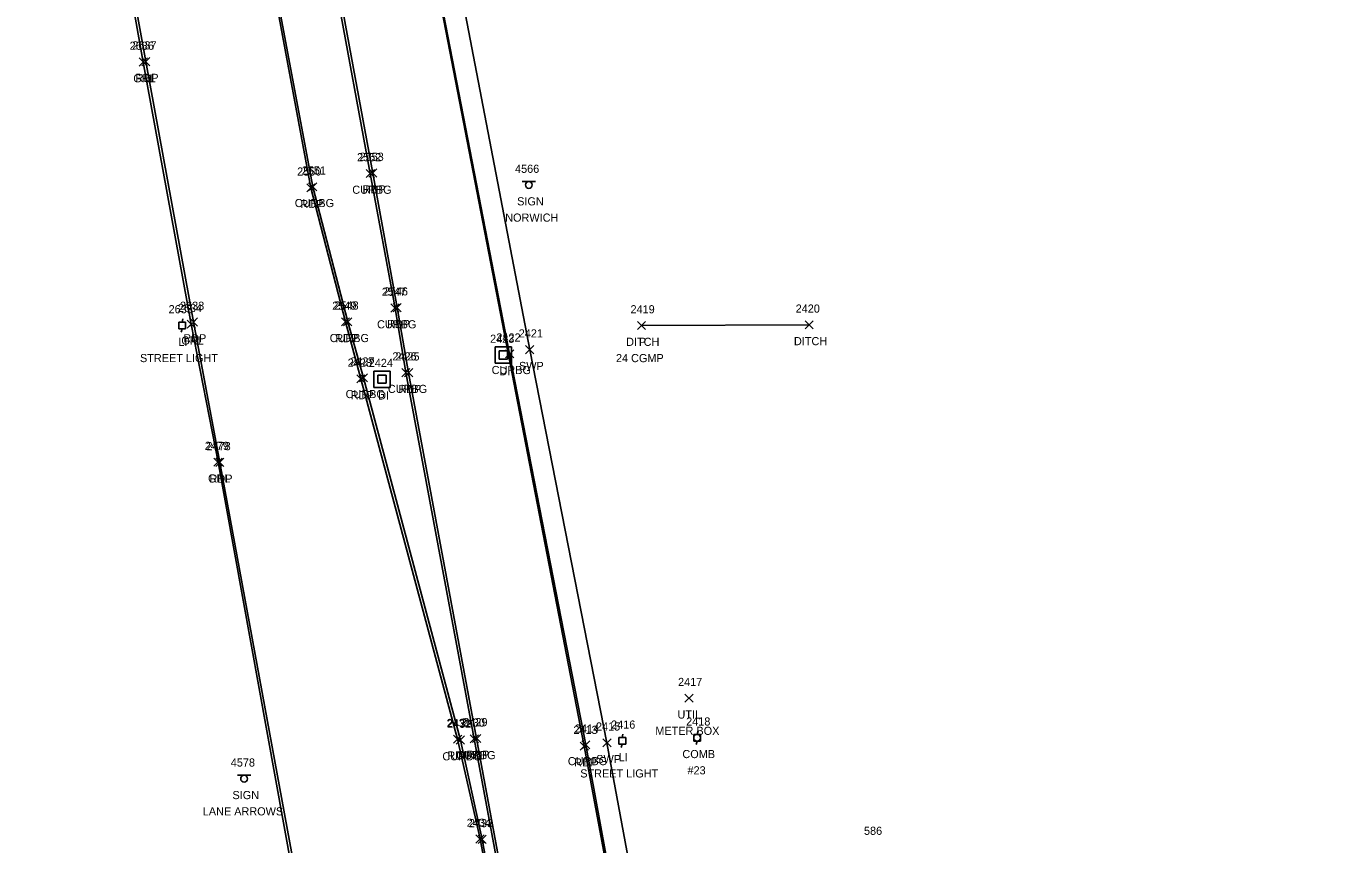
# Model space of a CAD drawing. Extents: x 1690689 to 1696275, y 438760 to 444007.
# Drawn here: x 1691233 to 1691552.4, y 440726.5 to 440927.5 of the extents above; entities that cross this region are included whole.
import ezdxf

# ---------------------------------------------------------------- set-up
doc = ezdxf.new("R2010")
doc.units = 0
for name, color, linetype in [('D_A', 7, 'Continuous'), ('D_C', 7, 'Continuous'), ('D_I', 7, 'Continuous'), ('D_TIC', 7, 'Continuous'), ('DD', 7, 'Continuous'), ('DS', 7, 'Continuous'), ('M_I', 7, 'Continuous'), ('P_A', 7, 'Continuous'), ('P_I', 7, 'Continuous'), ('P_TIC', 7, 'Continuous'), ('PET', 7, 'Continuous'), ('R_A', 7, 'Continuous'), ('R_I', 7, 'Continuous'), ('R_TIC', 7, 'Continuous'), ('RC', 7, 'Continuous'), ('RGR', 7, 'Continuous'), ('RSW', 7, 'Continuous'), ('S_A', 7, 'Continuous'), ('S_C', 7, 'Continuous'), ('S_I', 7, 'Continuous'), ('SSGN', 7, 'Continuous'), ('U_A', 7, 'Continuous'), ('U_C', 7, 'Continuous'), ('U_I', 7, 'Continuous'), ('UDEFAULT', 7, 'Continuous'), ('ULP', 7, 'Continuous'), ('UP', 7, 'Continuous')]:
    doc.layers.add(name, color=color, linetype=linetype)

msp = doc.modelspace()

# ---------------------------------------------------------------- linework, layer by layer
at = {"layer": 'D_TIC'}
for points in [[(1691383.37, 440852.89), (1691385.37, 440854.89)], [(1691385.37, 440852.89), (1691383.37, 440854.89)], [(1691383.37, 440852.89), (1691385.37, 440854.89)], [(1691385.37, 440852.89), (1691383.37, 440854.89)], [(1691424.61, 440853.06), (1691426.61, 440855.06)], [(1691426.61, 440853.06), (1691424.61, 440855.06)]]:
    msp.add_lwpolyline(points, dxfattribs=at)
at = {"layer": 'DD'}
msp.add_lwpolyline([(1691384.37, 440853.89), (1691425.61, 440854.06)], dxfattribs=at)
at = {"layer": 'DS'}
for p, q in [((1691348.4, 440848.65), (1691352.4, 440848.65)), ((1691348.4, 440844.65), (1691348.4, 440848.65)), ((1691349.4, 440845.65), (1691349.4, 440847.65)), ((1691349.4, 440847.65), (1691351.4, 440847.65)), ((1691350.41, 440846.65), (1691350.41, 440846.65)), ((1691350.41, 440846.65), (1691350.41, 440846.65)), ((1691351.4, 440847.65), (1691351.4, 440845.65)), ((1691352.4, 440848.65), (1691352.4, 440844.65)), ((1691352.4, 440844.65), (1691348.4, 440844.65)), ((1691351.4, 440845.65), (1691349.4, 440845.65)), ((1691318.57, 440842.7), (1691322.57, 440842.7)), ((1691318.57, 440838.7), (1691318.57, 440842.7)), ((1691319.57, 440839.7), (1691319.57, 440841.7)), ((1691319.57, 440841.7), (1691321.57, 440841.7)), ((1691320.57, 440840.71), (1691320.57, 440840.71)), ((1691320.57, 440840.71), (1691320.57, 440840.71)), ((1691321.57, 440841.7), (1691321.57, 440839.7)), ((1691322.57, 440842.7), (1691322.57, 440838.7)), ((1691322.57, 440838.7), (1691318.57, 440838.7)), ((1691321.57, 440839.7), (1691319.57, 440839.7))]:
    msp.add_line(p, q, dxfattribs=at)
at = {"layer": 'P_TIC'}
for points in [[(1691261.49, 440917.74), (1691263.49, 440919.74)], [(1691263.49, 440917.74), (1691261.49, 440919.74)], [(1691317.31, 440890.37), (1691319.31, 440892.37)], [(1691319.31, 440890.37), (1691317.31, 440892.37)], [(1691302.05, 440886.74), (1691304.05, 440888.74)], [(1691304.05, 440886.74), (1691302.05, 440888.74)], [(1691323.31, 440857.29), (1691325.31, 440859.29)], [(1691325.31, 440857.29), (1691323.31, 440859.29)], [(1691273.23, 440853.76), (1691275.23, 440855.76)], [(1691275.23, 440853.76), (1691273.23, 440855.76)], [(1691273.23, 440853.76), (1691275.23, 440855.76)], [(1691275.23, 440853.76), (1691273.23, 440855.76)], [(1691310.61, 440853.78), (1691312.61, 440855.78)], [(1691312.61, 440853.78), (1691310.61, 440855.78)], [(1691326.11, 440841.3), (1691328.11, 440843.3)], [(1691328.11, 440841.3), (1691326.11, 440843.3)], [(1691326.11, 440841.3), (1691328.11, 440843.3)], [(1691328.11, 440841.3), (1691326.11, 440843.3)], [(1691314.38, 440839.77), (1691316.38, 440841.77)], [(1691316.38, 440839.77), (1691314.38, 440841.77)], [(1691314.38, 440839.77), (1691316.38, 440841.77)], [(1691316.38, 440839.77), (1691314.38, 440841.77)], [(1691279.68, 440819.26), (1691281.68, 440821.26)], [(1691281.68, 440819.26), (1691279.68, 440821.26)], [(1691338.16, 440751.24), (1691340.16, 440753.24)], [(1691340.16, 440751.24), (1691338.16, 440753.24)], [(1691342.83, 440751.44), (1691344.83, 440753.44)], [(1691344.83, 440751.44), (1691342.83, 440753.44)], [(1691369.31, 440749.54), (1691371.31, 440751.54)], [(1691371.31, 440749.54), (1691369.31, 440751.54)], [(1691343.67, 440726.73), (1691345.67, 440728.73)], [(1691345.67, 440726.73), (1691343.67, 440728.73)]]:
    msp.add_lwpolyline(points, dxfattribs=at)
at = {"layer": 'PET'}
for points in [[(1691274.23, 440854.76), (1691262.49, 440918.74), (1691249.64, 440989.69), (1691246.21, 441008.07), (1691242.26, 441033.57), (1691238.51, 441080.26), (1691233.04, 441128.02)], [(1691552.42, 440436.47), (1691508.96, 440428.4), (1691494.48, 440424.84), (1691487.53, 440422.16), (1691479.98, 440421.74), (1691470.17, 440422.5), (1691465.43, 440423.73), (1691457.75, 440426.39), (1691450.59, 440430.36), (1691444.98, 440434.77), (1691439.4, 440439.84), (1691432.83, 440448.46), (1691425.81, 440467.29), (1691416.92, 440505.6), (1691412.15, 440527.64), (1691404.42, 440565.6), (1691397.74, 440602.52), (1691382.41, 440685.3), (1691370.31, 440750.54), (1691330.06, 440958.54), (1691316.82, 441030.69), (1691309.01, 441068.57), (1691294.14, 441127.58)], [(1691315.38, 440840.77), (1691311.61, 440854.78), (1691303.05, 440887.74), (1691293.73, 440938.05), (1691282.96, 440996.72), (1691276.31, 441056.08), (1691276.5, 441078.72), (1691277.07, 441079.98)], [(1691327.11, 440842.3), (1691324.31, 440858.29), (1691318.31, 440891.37), (1691310.01, 440936.22), (1691297.98, 441000.51), (1691285.01, 441057.44), (1691279.75, 441079.06), (1691279.06, 441080.28), (1691277.81, 441080.8), (1691277.07, 441079.98)], [(1691350.23, 440434.31), (1691349.02, 440445.67), (1691341.53, 440488.54), (1691328.03, 440562.61), (1691315.34, 440632.97), (1691299.08, 440720.53), (1691280.68, 440820.26), (1691274.23, 440854.76)], [(1691315.38, 440840.77), (1691339.16, 440752.24), (1691344.67, 440727.73), (1691359.12, 440649.27), (1691368.01, 440600.75), (1691385.38, 440506.23), (1691396.38, 440445.66), (1691403.64, 440405.97), (1691404.52, 440404.92)], [(1691327.11, 440842.3), (1691343.83, 440752.44), (1691362.78, 440649.9), (1691372.44, 440596.72), (1691388.92, 440507.28), (1691399.19, 440450.17), (1691407.2, 440406.4), (1691406.31, 440404.65), (1691404.52, 440404.92)]]:
    msp.add_lwpolyline(points, dxfattribs=at)
at = {"layer": 'R_TIC'}
for points in [[(1691260.88, 440917.64), (1691262.88, 440919.64)], [(1691262.88, 440917.64), (1691260.88, 440919.64)], [(1691316.69, 440890.26), (1691318.69, 440892.26)], [(1691318.69, 440890.26), (1691316.69, 440892.26)], [(1691302.54, 440886.99), (1691304.54, 440888.99)], [(1691304.54, 440886.99), (1691302.54, 440888.99)], [(1691322.78, 440857.19), (1691324.78, 440859.19)], [(1691324.78, 440857.19), (1691322.78, 440859.19)], [(1691272.69, 440853.21), (1691274.69, 440855.21)], [(1691274.69, 440853.21), (1691272.69, 440855.21)], [(1691272.69, 440853.21), (1691274.69, 440855.21)], [(1691274.69, 440853.21), (1691272.69, 440855.21)], [(1691311.13, 440853.82), (1691313.13, 440855.82)], [(1691313.13, 440853.82), (1691311.13, 440855.82)], [(1691350.95, 440845.96), (1691352.95, 440847.96)], [(1691352.95, 440845.96), (1691350.95, 440847.96)], [(1691355.89, 440846.96), (1691357.89, 440848.96)], [(1691357.89, 440846.96), (1691355.89, 440848.96)], [(1691325.44, 440841.32), (1691327.44, 440843.32)], [(1691327.44, 440841.32), (1691325.44, 440843.32)], [(1691325.44, 440841.32), (1691327.44, 440843.32)], [(1691327.44, 440841.32), (1691325.44, 440843.32)], [(1691315.03, 440840.06), (1691317.03, 440842.06)], [(1691317.03, 440840.06), (1691315.03, 440842.06)], [(1691315.03, 440840.06), (1691317.03, 440842.06)], [(1691317.03, 440840.06), (1691315.03, 440842.06)], [(1691279.26, 440819.33), (1691281.26, 440821.33)], [(1691281.26, 440819.33), (1691279.26, 440821.33)], [(1691338.83, 440751.04), (1691340.83, 440753.04)], [(1691340.83, 440751.04), (1691338.83, 440753.04)], [(1691342.27, 440751.33), (1691344.27, 440753.33)], [(1691344.27, 440751.33), (1691342.27, 440753.33)], [(1691369.67, 440749.86), (1691371.67, 440751.86)], [(1691371.67, 440749.86), (1691369.67, 440751.86)], [(1691374.88, 440750.37), (1691376.88, 440752.37)], [(1691376.88, 440750.37), (1691374.88, 440752.37)], [(1691344.19, 440726.63), (1691346.19, 440728.63)], [(1691346.19, 440726.63), (1691344.19, 440728.63)]]:
    msp.add_lwpolyline(points, dxfattribs=at)
at = {"layer": 'RC'}
for points in [[(1691450.76, 440430.58), (1691444.92, 440435.07), (1691439.78, 440439.75), (1691432.93, 440448.9), (1691426.12, 440467.24), (1691417.19, 440505.54), (1691412.4, 440527.61), (1691405.01, 440565.67), (1691398.01, 440602.6), (1691382.66, 440685.49), (1691370.67, 440750.86), (1691351.95, 440846.96), (1691330.25, 440958.42), (1691317.04, 441030.78), (1691309.36, 441068.61), (1691294.46, 441127.62), (1691280.16, 441186.14), (1691271.8, 441225.57)], [(1691316.03, 440841.06), (1691312.13, 440854.82), (1691303.54, 440887.99), (1691294.13, 440938.24), (1691283.53, 440996.84), (1691276.71, 441056.25), (1691277.13, 441078.83), (1691277.37, 441079.82)], [(1691326.44, 440842.32), (1691323.78, 440858.19), (1691317.69, 440891.26), (1691309.38, 440936.25), (1691297.2, 441000.25), (1691284.66, 441057.25), (1691279.32, 441078.94), (1691278.99, 441079.94), (1691278.1, 441080.23), (1691277.37, 441079.82)], [(1691316.03, 440841.06), (1691339.83, 440752.04), (1691345.19, 440727.63), (1691359.75, 440649.46), (1691368.41, 440600.85), (1691369.54, 440598.21)], [(1691326.44, 440842.32), (1691343.27, 440752.33), (1691362.34, 440649.71), (1691372.07, 440596.75), (1691388.57, 440507.07), (1691399.02, 440450.03), (1691406.75, 440406.47), (1691406.03, 440405.14), (1691404.87, 440405.37)]]:
    msp.add_lwpolyline(points, dxfattribs=at)
at = {"layer": 'RGR'}
for points in [[(1691273.69, 440854.21), (1691261.88, 440918.64), (1691249.24, 440989.46), (1691244.95, 441007.8), (1691238.22, 441030.27)], [(1691349.43, 440432.67), (1691348.1, 440445.44), (1691340.7, 440488.56), (1691327.21, 440562.16), (1691314.3, 440632.73), (1691298.42, 440720.43), (1691280.26, 440820.33), (1691273.69, 440854.21)]]:
    msp.add_lwpolyline(points, dxfattribs=at)
at = {"layer": 'RSW'}
msp.add_lwpolyline([(1691443.18, 440443.49), (1691437.15, 440451.8), (1691431.59, 440467.18), (1691422.3, 440506.42), (1691417.59, 440529.04), (1691409.95, 440566.67), (1691402.99, 440604.6), (1691387.94, 440685.95), (1691375.88, 440751.37), (1691356.89, 440847.96), (1691335.56, 440959.35), (1691322.05, 441031.91), (1691314.28, 441069.9), (1691299.65, 441129.23)], dxfattribs=at)
at = {"layer": 'SSGN'}
for p, q in [((1691355.02, 440889.26), (1691358.35, 440889.26)), ((1691356.66, 440888.43), (1691356.66, 440888.43)), ((1691285.02, 440743.37), (1691288.35, 440743.37)), ((1691286.67, 440742.54), (1691286.67, 440742.54))]:
    msp.add_line(p, q, dxfattribs=at)
for centre in [(1691356.66, 440888.43), (1691286.67, 440742.54)]:
    msp.add_circle(centre, 0.833, dxfattribs=at)
at = {"layer": 'UDEFAULT'}
for points in [[(1691395.06, 440761.31), (1691397.06, 440763.31)], [(1691397.06, 440761.31), (1691395.06, 440763.31)]]:
    msp.add_lwpolyline(points, dxfattribs=at)
at = {"layer": 'ULP'}
for p, q in [((1691270.58, 440853.07), (1691270.58, 440854.74)), ((1691270.58, 440854.74), (1691272.25, 440854.74)), ((1691272.25, 440853.07), (1691270.58, 440853.07)), ((1691271.16, 440852.24), (1691271.41, 440853.07)), ((1691271.58, 440855.57), (1691271.41, 440854.74)), ((1691271.41, 440853.9), (1691271.41, 440853.9)), ((1691272.25, 440854.74), (1691272.25, 440853.07)), ((1691378.81, 440751.01), (1691378.81, 440752.67)), ((1691378.81, 440752.67), (1691380.48, 440752.67)), ((1691380.48, 440751.01), (1691378.81, 440751.01)), ((1691379.4, 440750.17), (1691379.65, 440751.01)), ((1691379.81, 440753.51), (1691379.65, 440752.67)), ((1691379.65, 440751.84), (1691379.65, 440751.84)), ((1691380.48, 440752.67), (1691380.48, 440751.01))]:
    msp.add_line(p, q, dxfattribs=at)
at = {"layer": 'UP'}
for p, q in [((1691398.29, 440754.27), (1691398.04, 440753.43)), ((1691397.21, 440751.77), (1691397.21, 440753.43)), ((1691397.21, 440753.43), (1691398.88, 440753.43)), ((1691398.88, 440751.77), (1691397.21, 440751.77)), ((1691397.79, 440750.93), (1691398.04, 440751.77)), ((1691398.04, 440752.6), (1691398.04, 440752.6)), ((1691398.88, 440753.43), (1691398.88, 440751.77))]:
    msp.add_line(p, q, dxfattribs=at)
msp.add_circle((1691398.04, 440752.6), 0.833, dxfattribs=at)

# ---------------------------------------------------------------- texts
at = {"layer": 'D_A'}
for s, p in [('DITCH', (1691380.6, 440848.89)), ('P', (1691383.74, 440848.89)), ('DITCH', (1691421.85, 440849.06)), ('DI', (1691349.46, 440841.65)), ('DI', (1691319.63, 440835.71))]:
    msp.add_text(s, height=2, dxfattribs=at).set_placement(p)
at = {"layer": 'D_C'}
msp.add_text('24 CGMP', height=2, dxfattribs=at).set_placement((1691378.09, 440844.89))
at = {"layer": 'D_I'}
for s, p in [('2420', (1691422.27, 440857.06)), ('2419', (1691381.67, 440856.89)), ('2419', (1691381.67, 440856.89)), ('2423', (1691347.15, 440849.65)), ('2424', (1691317.31, 440843.71))]:
    msp.add_text(s, height=2, dxfattribs=at).set_placement(p)
at = {"layer": 'M_I'}
msp.add_text('586', height=2, dxfattribs=at).set_placement((1691439.07, 440728.74))
at = {"layer": 'P_A'}
for p in [(1691259.98, 440913.74), (1691315.8, 440886.37), (1691300.53, 440882.74), (1691321.8, 440853.29), (1691271.72, 440849.76), (1691271.72, 440849.76), (1691309.1, 440849.78), (1691312.87, 440835.77), (1691312.87, 440835.77), (1691324.6, 440837.3), (1691324.6, 440837.3), (1691278.17, 440815.26), (1691336.65, 440747.24), (1691341.31, 440747.44), (1691367.8, 440745.54)]:
    msp.add_text('RDP', height=2, dxfattribs=at).set_placement(p)
at = {"layer": 'P_I'}
for s, p in [('2637', (1691259.19, 440921.74)), ('2553', (1691315.05, 440894.37)), ('2550', (1691299.7, 440890.74)), ('2546', (1691321, 440861.29)), ('2633', (1691270.92, 440857.76)), ('2633', (1691270.92, 440857.76)), ('2549', (1691308.34, 440857.78)), ('2425', (1691323.85, 440845.3)), ('2425', (1691323.85, 440845.3)), ('2428', (1691312.12, 440843.77)), ('2428', (1691312.12, 440843.77)), ('2478', (1691277.42, 440823.26)), ('2431', (1691336.47, 440755.24)), ('2429', (1691340.56, 440755.44)), ('2413', (1691367.62, 440753.54)), ('2434', (1691341.41, 440730.73))]:
    msp.add_text(s, height=2, dxfattribs=at).set_placement(p)
at = {"layer": 'R_A'}
for s, p in [('GRL', (1691259.42, 440913.64)), ('CURBG', (1691313.27, 440886.26)), ('CURBG', (1691299.12, 440882.99)), ('CURBG', (1691319.36, 440853.19)), ('GRL', (1691271.23, 440849.21)), ('GRL', (1691271.23, 440849.21)), ('CURBG', (1691307.71, 440849.82)), ('CURBG', (1691347.53, 440841.96)), ('SWP', (1691354.25, 440842.96)), ('CURBG', (1691311.62, 440836.06)), ('CURBG', (1691311.62, 440836.06)), ('CURBG', (1691322.02, 440837.32)), ('CURBG', (1691322.02, 440837.32)), ('GRL', (1691277.8, 440815.33)), ('CURBG', (1691335.41, 440747.04)), ('CURBG', (1691338.85, 440747.33)), ('CURBG', (1691366.26, 440745.86)), ('SWP', (1691373.25, 440746.37))]:
    msp.add_text(s, height=2, dxfattribs=at).set_placement(p)
at = {"layer": 'R_I'}
for s, p in [('2636', (1691258.52, 440921.64)), ('2552', (1691314.43, 440894.26)), ('2551', (1691300.85, 440890.99)), ('2547', (1691320.52, 440861.19)), ('2634', (1691270.38, 440857.21)), ('2634', (1691270.38, 440857.21)), ('2548', (1691308.87, 440857.82)), ('2421', (1691354.19, 440850.96)), ('2422', (1691348.69, 440849.96)), ('2426', (1691323.13, 440845.32)), ('2426', (1691323.13, 440845.32)), ('2427', (1691312.77, 440844.06)), ('2427', (1691312.77, 440844.06)), ('2479', (1691276.99, 440823.33)), ('2432', (1691336.57, 440755.04)), ('2430', (1691339.92, 440755.33)), ('2414', (1691367.98, 440753.86)), ('2415', (1691373.19, 440754.37)), ('2433', (1691341.93, 440730.63))]:
    msp.add_text(s, height=2, dxfattribs=at).set_placement(p)
at = {"layer": 'S_A'}
for p in [(1691353.8, 440883.41), (1691283.81, 440737.52)]:
    msp.add_text('SIGN', height=2, dxfattribs=at).set_placement(p)
at = {"layer": 'S_C'}
for s, p in [('NORWICH', (1691350.86, 440879.41)), ('LANE ARROWS', (1691276.51, 440733.52))]:
    msp.add_text(s, height=2, dxfattribs=at).set_placement(p)
at = {"layer": 'S_I'}
for s, p in [('4566', (1691353.28, 440891.41)), ('4578', (1691283.39, 440745.52))]:
    msp.add_text(s, height=2, dxfattribs=at).set_placement(p)
at = {"layer": 'U_A'}
for s, p in [('LI', (1691270.51, 440848.9)), ('UTIL', (1691393.22, 440757.31)), ('LI', (1691378.75, 440746.84)), ('COMB', (1691394.43, 440747.6))]:
    msp.add_text(s, height=2, dxfattribs=at).set_placement(p)
at = {"layer": 'U_C'}
for s, p in [('STREET LIGHT', (1691261.07, 440844.9)), ('METER BOX', (1691387.77, 440753.31)), ('STREET LIGHT', (1691369.31, 440742.84)), ('#23', (1691395.68, 440743.6))]:
    msp.add_text(s, height=2, dxfattribs=at).set_placement(p)
at = {"layer": 'U_I'}
for s, p in [('2635', (1691268.1, 440856.9)), ('2417', (1691393.36, 440765.31)), ('2416', (1691376.9, 440754.84)), ('2418', (1691395.35, 440755.6))]:
    msp.add_text(s, height=2, dxfattribs=at).set_placement(p)

doc.saveas('drawing.dxf')
